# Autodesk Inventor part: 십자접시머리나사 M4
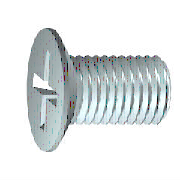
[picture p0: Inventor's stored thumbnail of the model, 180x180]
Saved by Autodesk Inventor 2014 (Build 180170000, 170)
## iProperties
IsCustomPart: 0
Created: 2012-02
Part Number: 십자접시머리나사 M4
Material: 강철, 연강
Description: 십자 오목 머리 나사
Document SubType Name: Modeling
Standard: KS B 1023
Designer: mduedu
Standards Organization: KS
Language: ko-KR
Size Designation: A  M 4 x 12 - H
Categories: <MemberInstance><Categories><Category DisplayName="조임쇠" InternalName="e4da775c-781d-43d5-af7c-5136215cf5a6" Mnemonic="FSTN"><Category DisplayName="볼트" InternalN
Density: 7.86 g/cm^3
Mass: 1.5048 g
Surface Area: 2.78557 cm^2
Volume: 0.191451 cm^3
Appearance: 주황색
Author: mduedu
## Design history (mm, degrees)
body "Solid1"
sketch "스케치1"
  geometry: L1 (2.6, 0)-(12, 0); L2 (12, 0)-(12, 2); L3 (12, 2)-(4.1, 2); L4 (4.1, 2)-(3.671, 1.785); L5 (3.671, 1.785)-(2.7, 1.785); L6 (0, 4.2)-(0, 2.4); L7 (0, 2.4)-(1.801, 1.502); L8 (1.801, 1.502)-(2.6, 0); L9 (-2.4, 0)-(14.4, 0) reference; L10 (0, -0.84)-(0, 5.04) reference; L11 (0, 4.2)-(0.285, 4.2); L12 (0.285, 4.2)-(2.7, 1.785); L13 (4.1, 2)-(2.485, 2)
  constraints: 22 end point, 3 parallel, 3 perpendicular, 2 collinear, 1 horizontal, 1 point on line
  dimensions: "d1" = 7.9 distance of L2.end L3.end (= GEL); "d2" = 4 diameter of L3 L1 (= GD); "d3" = 3.57058 diameter of L5 L1 (= BDM); "d4" = 4.8 diameter of L6.end L1 (= SDM); "d5" = 26.5 deg angle of L7 L1; "d6" = 62 deg angle of L8 L1; "d7" = 2.6 distance from line of L1.start L6 (= INTI); "d8" = 0.42941 horizontal distance of L4.end L3.end (= GAL); "d12" = 8.4 diameter of L11 L1 (= KOD); "d13" = 45 deg angle of L12 L1 (= 0.5 x SEWI); "d15" = 12 distance between parallel lines of L2 L6 (= NLG); "d24" = 2.7 distance from line of L5.end L6 (= KOH)
revolve "본체" stored, may be unused: angle "d16" = 90 deg
sketch "스케치2"
  geometry: L1 (0, 2.4)-(0, 0); L2 (0, 0)-(2.4, 0); L3 (0, 0)-(1.697, 1.697); L4 (0.312, 2.38)-(0.408, 0.734); L5 (2.38, 0.312)-(0.734, 0.408); L6 (0, -5.88)-(0, 5.88) reference; L7 (-5.88, 0)-(5.88, 0) reference; L8 (2.38, -0.312)-(0.734, -0.408); L9 (0.312, -2.38)-(0.408, -0.734); L10 (-0.312, -2.38)-(-0.408, -0.734); L11 (-2.38, -0.312)-(-0.734, -0.408); L12 (-2.38, 0.312)-(-0.734, 0.408); L13 (-0.312, 2.38)-(-0.408, 0.734); A1 r 0.72 centre (0, 0) between (0.72, 0) and (0, 0.72); A2 r 0.84 centre (0, 0) between (0.84, 0) and (0, 0.84); A3 r 2.4 centre (0, 0) between (2.38, 0.312) and (0.312, 2.38); A4 r 2.4 centre (0, 0) between (0.312, 2.38) and (0, 2.4); A5 r 2.4 centre (0, 0) between (2.4, 0) and (2.38, 0.312); A6 r 2.4 centre (0, 0) between (0, -2.4) and (0.312, -2.38); A7 r 2.4 centre (0, 0) between (0.312, -2.38) and (2.38, -0.312); A8 r 2.4 centre (0, 0) between (2.38, -0.312) and (2.4, 0); A9 r 2.4 centre (0, 0) between (0, 2.4) and (-0.312, 2.38); A10 r 2.4 centre (0, 0) between (-0.312, 2.38) and (-2.38, 0.312); A11 r 2.4 centre (0, 0) between (-2.38, 0.312) and (-2.4, 0); A12 r 2.4 centre (0, 0) between (-2.4, 0) and (-2.38, -0.312); A13 r 2.4 centre (0, 0) between (-2.38, -0.312) and (-0.312, -2.38); A14 r 2.4 centre (0, 0) between (-0.312, -2.38) and (0, -2.4); A15 r 0.347 centre (0.755, 0.755) between (0.408, 0.734) and (0.734, 0.408); A16 r 0.347 centre (0.755, -0.755) between (0.734, -0.408) and (0.408, -0.734); A17 r 0.347 centre (-0.755, -0.755) between (-0.408, -0.734) and (-0.734, -0.408); A18 r 0.347 centre (-0.755, 0.755) between (-0.734, 0.408) and (-0.408, 0.734); 3 further points
  constraints: 41 point on circle, 22 end point, 22 symmetric about line, 18 centre point, 11 coincident, 4 point on line, 3 tangent, 2 collinear, 1 perpendicular, 1 vertical, 19 other
  dimensions: "d17" = 1.44 diameter of A1 (= 0.3 x SDM); "d18" = 1.68 diameter of A2 (= 0.35 x SDM); "d19" = 4.8 diameter of A3 (= SDM); "d20" = 45 deg angle of L3 L2; "d21" = 0.3115 distance from line of L4.start L1 (= 0.5 x SBR)
extrude "슬롯" join sketch "스케치2" taper "d22" = 5 deg; stored distance "d79" = 25.4
fillet "모깎기1" dims "d23" = 0.1246 (= 0.2 x SBR)
feature "스레드" dims "d10" = 7.9 (= GEL), "d11" = 0
chamfer "모따기1" distance "d25" = 0.42941 (= -0.5 x SPD + 0.5 x GD); stored, may be unused: second distance "d26" = 0.21471 (= 0.5 x GAL), angle "d88" = 45 deg
workplane "Work Plane2"
other parameters: "NLG" = 12 [user parameter; used in 1 equation term], "GEL" = 7.9 [user parameter; used in 2 equation terms], "GAL" = 0.42941 (= 0.61345 x PTC) [user parameter; used in 3 equation terms], "SPD" = 3.14117 (= NND - 1.2269 x PTC) [user parameter; used in 1 equation term], "KOD" = 8.4 [user parameter; used in 1 equation term], "KOH" = 2.7 [user parameter; used in 1 equation term], "SBR" = 0.623 [user parameter; used in 2 equation terms], "INTI" = 2.6 [user parameter; used in 1 equation term], "SDM" = 4.8 [user parameter; used in 5 equation terms], "GD" = 4 (= NND) [user parameter; used in 2 equation terms], "BDM" = 3.57058 (= NND - GAL) [user parameter; used in 1 equation term], "SEWI" = 90 deg [user parameter; used in 1 equation term], "d9" = 4.8 (= SDM), "d27" = 0, "d91" = 0, "d92" = 0, "GUL" = 0.42941 (= 0.61345 x PTC) [user parameter], "TOA" = 30 deg [user parameter], "EPV" = 4.7 [user parameter], "THREADDIA" = 4 [user parameter; used in 1 equation term], "TPU" = 14.28571 (computed from PTC) [user parameter], "PTC" = 0.7 [user parameter; used in 5 equation terms], "NND" = 4 [user parameter; used in 3 equation terms], "GD1" = 3.14117 (= THREADDIA - 1.2269 x PTC) [user parameter]
